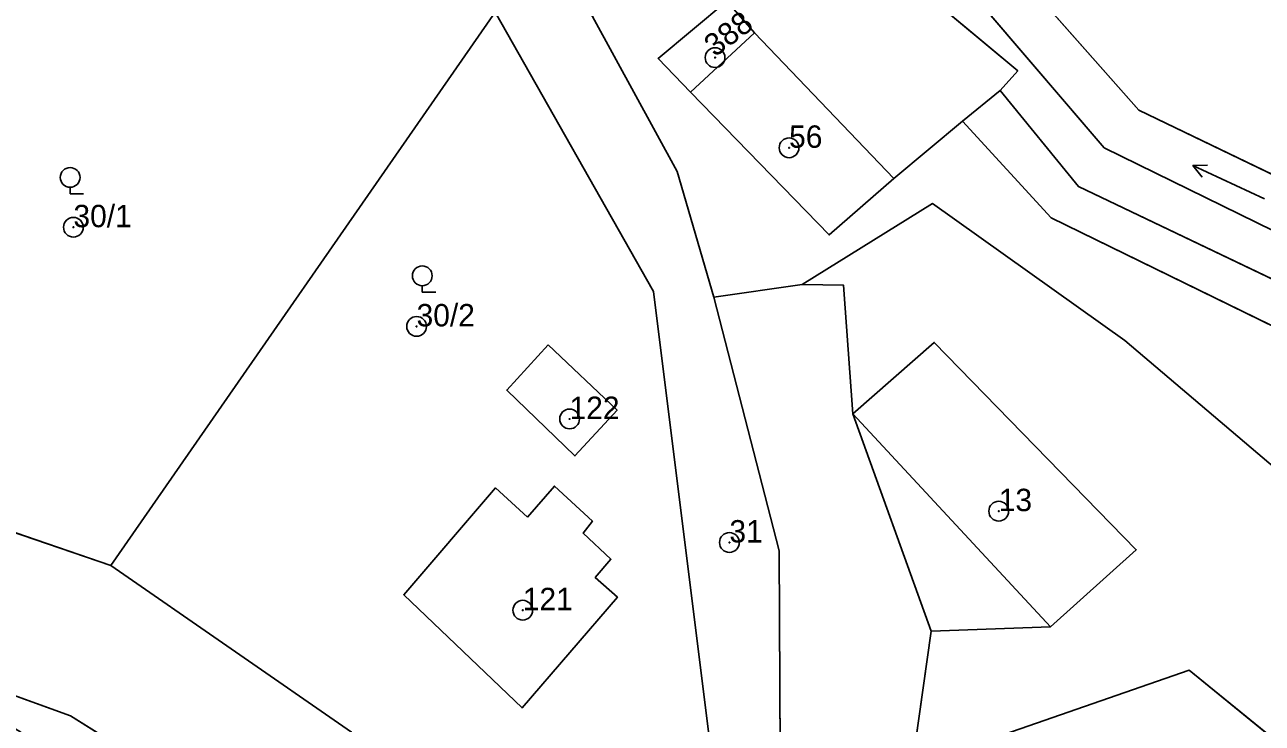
# Model space of a CAD drawing. Extents: x -652854 to -650068, y -1097661 to -1095417.
# Drawn here: x -650913.5 to -650819.6, y -1095999.2 to -1095946.2 of the extents above; entities that cross this region are included whole.
import ezdxf

# ---------------------------------------------------------------- set-up
doc = ezdxf.new("R2010")
doc.units = 0
for name, color, linetype in [('Definiční body parcel', 7, 'Continuous'), ('Hranice - vnitř_ kresba', 7, 'Continuous'), ('Hranice parcel', 7, 'Continuous'), ('Obvody jako plochy', 7, 'Continuous'), ('Parcelní čísla', 7, 'Continuous'), ('Značky kultur', 7, 'Continuous')]:
    doc.layers.add(name, color=color, linetype=linetype)

msp = doc.modelspace()

# ---------------------------------------------------------------- linework, layer by layer
at = {"layer": 'Definiční body parcel'}
for centre, radius in [((-650861.12, -1095948.68), 0.75), ((-650861.12, -1095948.68), 0.0327), ((-650855.5, -1095955.53), 0.75), ((-650855.5, -1095955.53), 0.0327), ((-650909.81, -1095961.56), 0.75), ((-650909.81, -1095961.56), 0.0327), ((-650883.77, -1095969.09), 0.75), ((-650883.77, -1095969.09), 0.0327), ((-650872.16, -1095976.12), 0.75), ((-650872.16, -1095976.12), 0.0327), ((-650839.59, -1095983.12), 0.75), ((-650839.59, -1095983.12), 0.0327), ((-650860.03, -1095985.5), 0.75), ((-650860.03, -1095985.5), 0.0327), ((-650875.71, -1095990.64), 0.75), ((-650875.71, -1095990.64), 0.0327)]:
    msp.add_circle(centre, radius, dxfattribs=at)
at = {"layer": 'Hranice - vnitř_ kresba'}
for p, q in [((-650858.12, -1095946.81), (-650847.56, -1095957.86)), ((-650835.66, -1095991.9), (-650850.67, -1095975.72))]:
    msp.add_line(p, q, dxfattribs=at)
at = {"layer": 'Hranice parcel'}
for p, q in [((-650869.65, -1095911.01), (-650831.59, -1095955.54)), ((-650840.77, -1095939.29), (-650828.97, -1095952.68)), ((-650838.15, -1095949.69), (-650846.62, -1095942.61)), ((-650860.23, -1095944.4), (-650865.44, -1095948.76)), ((-650860.23, -1095944.4), (-650858.12, -1095946.81)), ((-650906.97, -1095987.24), (-650877.8, -1095945.22)), ((-650865.79, -1095966.45), (-650877.8, -1095945.22)), ((-650864, -1095957.32), (-650870.42, -1095945.56)), ((-650858.12, -1095946.81), (-650862.98, -1095951.3)), ((-650865.44, -1095948.76), (-650862.98, -1095951.3)), ((-650839.47, -1095951.17), (-650838.15, -1095949.69)), ((-650862.98, -1095951.3), (-650852.46, -1095962.14)), ((-650842.35, -1095953.5), (-650839.47, -1095951.17)), ((-650833.55, -1095958.46), (-650839.47, -1095951.17)), ((-650828.97, -1095952.68), (-650768.13, -1095982)), ((-650847.56, -1095957.86), (-650842.35, -1095953.5)), ((-650842.35, -1095953.5), (-650835.62, -1095960.85)), ((-650831.59, -1095955.54), (-650760.98, -1095990.15)), ((-650861.2, -1095966.88), (-650864, -1095957.32)), ((-650852.46, -1095962.14), (-650847.56, -1095957.86)), ((-650767.4, -1095990.09), (-650833.55, -1095958.46)), ((-650844.61, -1095959.76), (-650854.5, -1095965.91)), ((-650830.01, -1095970.16), (-650844.61, -1095959.76)), ((-650835.62, -1095960.85), (-650766.86, -1095994.47)), ((-650854.5, -1095965.91), (-650861.2, -1095966.88)), ((-650854.5, -1095965.91), (-650851.37, -1095965.97)), ((-650851.37, -1095965.97), (-650850.67, -1095975.72)), ((-650861.57, -1096000.28), (-650865.79, -1095966.45)), ((-650861.2, -1095966.88), (-650856.25, -1095986.12)), ((-650873.78, -1095970.5), (-650876.93, -1095973.93)), ((-650868.55, -1095975.44), (-650873.78, -1095970.5)), ((-650850.67, -1095975.72), (-650844.49, -1095970.31)), ((-650844.49, -1095970.31), (-650829.16, -1095986.05)), ((-650818.08, -1095980.3), (-650830.01, -1095970.16)), ((-650876.93, -1095973.93), (-650871.76, -1095978.92)), ((-650871.76, -1095978.92), (-650868.55, -1095975.44)), ((-650850.67, -1095975.72), (-650844.73, -1095992.23)), ((-650877.78, -1095981.35), (-650884.74, -1095989.47)), ((-650875.34, -1095983.57), (-650877.78, -1095981.35)), ((-650873.31, -1095981.22), (-650875.34, -1095983.57)), ((-650870.43, -1095983.89), (-650873.31, -1095981.22)), ((-650906.97, -1095987.24), (-650919.07, -1095983.1)), ((-650871.13, -1095984.79), (-650870.43, -1095983.89)), ((-650869.02, -1095986.77), (-650871.13, -1095984.79)), ((-650829.16, -1095986.05), (-650835.66, -1095991.9)), ((-650870.21, -1095988.15), (-650869.02, -1095986.77)), ((-650856.25, -1095986.12), (-650856.19, -1096001.44)), ((-650888.72, -1095999.9), (-650906.97, -1095987.24)), ((-650868.53, -1095989.66), (-650870.21, -1095988.15)), ((-650884.74, -1095989.47), (-650875.76, -1095998.06)), ((-650875.76, -1095998.06), (-650868.53, -1095989.66)), ((-650928.95, -1095991.79), (-650910.04, -1095998.66)), ((-650847.08, -1096008.9), (-650844.73, -1095992.23)), ((-650844.73, -1095992.23), (-650835.66, -1095991.9)), ((-650839.79, -1096000.27), (-650825.13, -1095995.2)), ((-650825.13, -1095995.2), (-650797.14, -1096017.98)), ((-650895.24, -1096007.92), (-650910.04, -1095998.66))]:
    msp.add_line(p, q, dxfattribs=at)
at = {"layer": 'Obvody jako plochy'}
for points in [[(-650815.91, -1096079.94), (-650837.43, -1096057.82), (-650851.49, -1096042.56), (-650856.61, -1096037.55), (-650866.08, -1096025.56), (-650869.83, -1096021.1), (-650878.58, -1096010.13), (-650884.15, -1096004.16), (-650888.72, -1095999.9), (-650906.97, -1095987.24), (-650919.07, -1095983.1), (-650939.79, -1095976.94), (-650942.73, -1095975.31), (-650965.11, -1095955.28), (-650999.89, -1095931.88), (-651069.69, -1095883.2), (-651088.16, -1095874.33), (-651093.24, -1095871.75), (-651106.05, -1095871.75), (-651124.53, -1095872.94)], [(-651111.53, -1095882.37), (-651098.01, -1095884.51), (-651076.72, -1095891.08), (-651069.09, -1095896.55), (-651006, -1095940.92), (-650970.52, -1095965.45), (-650947.06, -1095985.27), (-650941.58, -1095987.24), (-650928.95, -1095991.79), (-650910.04, -1095998.66), (-650895.24, -1096007.92), (-650885.14, -1096017.44), (-650874.29, -1096030.48), (-650868.81, -1096038.2), (-650844.12, -1096064.27), (-650836.01, -1096073.17), (-650788.5, -1096124.42)], [(-650768.13, -1095982), (-650828.97, -1095952.68), (-650840.77, -1095939.29), (-650843.42, -1095936.19), (-650850.06, -1095928.49), (-650851.8, -1095929.96), (-650869.65, -1095911.01), (-650831.59, -1095955.54), (-650760.98, -1095990.15)], [(-650817.24, -1095917.02), (-650840.77, -1095939.29), (-650828.97, -1095952.68), (-650768.13, -1095982)], [(-650766.86, -1095994.47), (-650835.62, -1095960.85), (-650842.35, -1095953.5), (-650847.56, -1095957.86), (-650852.46, -1095962.14), (-650862.98, -1095951.3), (-650865.44, -1095948.76), (-650860.23, -1095944.4), (-650855.44, -1095943.79), (-650864.09, -1095938.47), (-650870.42, -1095945.56), (-650864, -1095957.32), (-650861.2, -1095966.88), (-650854.5, -1095965.91), (-650844.61, -1095959.76), (-650830.01, -1095970.16), (-650818.08, -1095980.3)]]:
    msp.add_lwpolyline(points, dxfattribs=at)
for points in [[(-650839.47, -1095951.17), (-650833.55, -1095958.46), (-650767.4, -1095990.09), (-650750.01, -1095996.81), (-650760.98, -1095990.15), (-650831.59, -1095955.54), (-650869.65, -1095911.01), (-650872.2, -1095913.61), (-650846.62, -1095942.61), (-650838.15, -1095949.69)], [(-650861.2, -1095966.88), (-650864, -1095957.32), (-650870.42, -1095945.56), (-650883.1, -1095928.38), (-650889.88, -1095920.1), (-650889.39, -1095918.87), (-650896.67, -1095915.35), (-650898.83, -1095918.21), (-650888.97, -1095929.69), (-650880.92, -1095939.45), (-650877.8, -1095945.22), (-650865.79, -1095966.45), (-650861.57, -1096000.28), (-650869.83, -1096021.1), (-650866.08, -1096025.56), (-650856.19, -1096001.44), (-650856.25, -1095986.12)], [(-650919.07, -1095983.1), (-650906.97, -1095987.24), (-650877.8, -1095945.22), (-650880.92, -1095939.45), (-650885.57, -1095945.44), (-650887.79, -1095943.89), (-650889.01, -1095945.42), (-650908.63, -1095932.22), (-650915.66, -1095942.26), (-650939.79, -1095976.94)], [(-650852.46, -1095962.14), (-650847.56, -1095957.86), (-650842.35, -1095953.5), (-650839.47, -1095951.17), (-650838.15, -1095949.69), (-650846.62, -1095942.61), (-650851.27, -1095943.21), (-650855.44, -1095943.79), (-650860.23, -1095944.4), (-650858.12, -1095946.81), (-650862.98, -1095951.3)], [(-650860.23, -1095944.4), (-650865.44, -1095948.76), (-650862.98, -1095951.3), (-650858.12, -1095946.81)], [(-650869.83, -1096021.1), (-650861.57, -1096000.28), (-650865.79, -1095966.45), (-650877.8, -1095945.22), (-650906.97, -1095987.24), (-650888.72, -1095999.9), (-650884.15, -1096004.16), (-650878.58, -1096010.13)], [(-650842.35, -1095953.5), (-650835.62, -1095960.85), (-650766.86, -1095994.47), (-650746.17, -1096002.75), (-650750.01, -1095996.81), (-650767.4, -1095990.09), (-650833.55, -1095958.46), (-650839.47, -1095951.17)], [(-650844.61, -1095959.76), (-650854.5, -1095965.91), (-650851.37, -1095965.97), (-650850.67, -1095975.72), (-650844.49, -1095970.31), (-650829.16, -1095986.05), (-650835.66, -1095991.9), (-650844.73, -1095992.23), (-650847.08, -1096008.9), (-650856.61, -1096037.55), (-650851.49, -1096042.56), (-650851, -1096035.98), (-650839.79, -1096000.27), (-650825.13, -1095995.2), (-650797.14, -1096017.98), (-650789.35, -1096010.06), (-650786.65, -1096007.6), (-650818.08, -1095980.3), (-650830.01, -1095970.16)], [(-650854.5, -1095965.91), (-650861.2, -1095966.88), (-650856.25, -1095986.12), (-650856.19, -1096001.44), (-650866.08, -1096025.56), (-650856.61, -1096037.55), (-650847.08, -1096008.9), (-650844.73, -1095992.23), (-650850.67, -1095975.72), (-650851.37, -1095965.97)], [(-650873.78, -1095970.5), (-650876.93, -1095973.93), (-650871.76, -1095978.92), (-650868.55, -1095975.44)], [(-650873.78, -1095970.5), (-650868.55, -1095975.44), (-650871.76, -1095978.92), (-650876.93, -1095973.93)], [(-650850.67, -1095975.72), (-650844.73, -1095992.23), (-650835.66, -1095991.9), (-650829.16, -1095986.05), (-650844.49, -1095970.31)], [(-650875.34, -1095983.57), (-650877.78, -1095981.35), (-650884.74, -1095989.47), (-650875.76, -1095998.06), (-650868.53, -1095989.66), (-650870.21, -1095988.15), (-650869.02, -1095986.77), (-650871.13, -1095984.79), (-650870.43, -1095983.89), (-650873.31, -1095981.22)], [(-650875.34, -1095983.57), (-650873.31, -1095981.22), (-650870.43, -1095983.89), (-650871.13, -1095984.79), (-650869.02, -1095986.77), (-650870.21, -1095988.15), (-650868.53, -1095989.66), (-650875.76, -1095998.06), (-650884.74, -1095989.47), (-650877.78, -1095981.35)], [(-650913.95, -1095999.79), (-650900.46, -1096009.94), (-650891.33, -1096018.28), (-650878.59, -1096032.13), (-650875.52, -1096037.79), (-650874.29, -1096030.48), (-650885.14, -1096017.44), (-650895.24, -1096007.92), (-650910.04, -1095998.66), (-650928.95, -1095991.79)], [(-650851.49, -1096042.56), (-650837.43, -1096057.82), (-650797.14, -1096017.98), (-650825.13, -1095995.2), (-650839.79, -1096000.27), (-650851, -1096035.98)]]:
    msp.add_lwpolyline(points, close=True, dxfattribs=at)
at = {"layer": 'Značky kultur'}
for p, q in [((-650819.421, -1095959.417), (-650824.859, -1095956.883)), ((-650910.06, -1095958.53), (-650910.06, -1095959.03)), ((-650910.06, -1095959.03), (-650909.037, -1095959.03)), ((-650883.34, -1095966), (-650883.34, -1095966.5)), ((-650883.34, -1095966.5), (-650882.317, -1095966.5))]:
    msp.add_line(p, q, dxfattribs=at)
msp.add_lwpolyline([(-650824.164, -1095957.758), (-650824.859, -1095956.883), (-650823.742, -1095956.852)], dxfattribs=at)
for centre in [(-650910.06, -1095957.78), (-650883.34, -1095965.25)]:
    msp.add_circle(centre, 0.75, dxfattribs=at)

# ---------------------------------------------------------------- texts
at = {"layer": 'Parcelní čísla'}
msp.add_text('388', height=1.7, rotation=37.116, dxfattribs=at).set_placement((-650861.12, -1095948.68))
for s, p in [('56', (-650855.5, -1095955.53)), ('30/1', (-650909.81, -1095961.56)), ('30/2', (-650883.77, -1095969.09)), ('122', (-650872.16, -1095976.12)), ('13', (-650839.59, -1095983.12)), ('31', (-650860.03, -1095985.5)), ('121', (-650875.71, -1095990.64))]:
    msp.add_text(s, height=1.7, dxfattribs=at).set_placement(p)

doc.saveas('drawing.dxf')
